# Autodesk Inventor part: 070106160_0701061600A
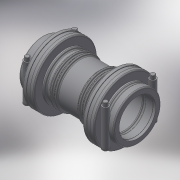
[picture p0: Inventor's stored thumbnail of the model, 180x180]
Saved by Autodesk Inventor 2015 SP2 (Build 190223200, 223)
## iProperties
Created: 2017-05
Part Number: 070106160_0701061600A
Material: Generic
Description: PLASSON COUPLER 160-160
Document SubType Name: Modeling
Designer: KIM
Density: 1 g/cm^3
Appearance: Default
Author: KIM
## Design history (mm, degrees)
derived "070106.ipt"
feature "Solid1::070106.ipt"
tag "TaggingFeature1"
body "Solid1"
other parameters: "d0" = 209, "d3" = 208, "d4" = 192, "d5" = 4.8, "d6" = 51, "d7" = 274.4, "d8" = 144, "d9" = 204, "d10" = 51, "d11" = 9.6, "d12" = 51, "d13" = 10.2, "d15" = 4.8, "d17" = 161.6, "d18" = 11.55, "d19" = 0, "d21" = 0, "d23" = 20.16, "d24" = 16, "d25" = 0, "d26" = 1.6, "d29" = 0.1, "d30" = 8, "d31" = 0, "d32" = 4.8, "l_" = 204, "H_" = 418, "d16" = 46.2, "d22" = 28.8
